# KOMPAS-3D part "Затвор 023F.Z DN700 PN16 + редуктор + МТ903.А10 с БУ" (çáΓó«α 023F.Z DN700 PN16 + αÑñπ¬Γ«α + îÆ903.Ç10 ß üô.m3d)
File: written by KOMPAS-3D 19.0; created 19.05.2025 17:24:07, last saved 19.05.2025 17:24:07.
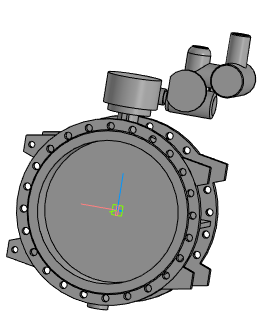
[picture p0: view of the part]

Document properties: Полное имя файла: Затвор 023F.Z DN700 PN16 + редуктор + МТ903.А10 с БУ.a3d

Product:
- Part/product: Затвор 023F.Z DN700 PN16 + редуктор + МТ903.А10 с БУ
    Масса: 720.986

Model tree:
1. Операция без истории:1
